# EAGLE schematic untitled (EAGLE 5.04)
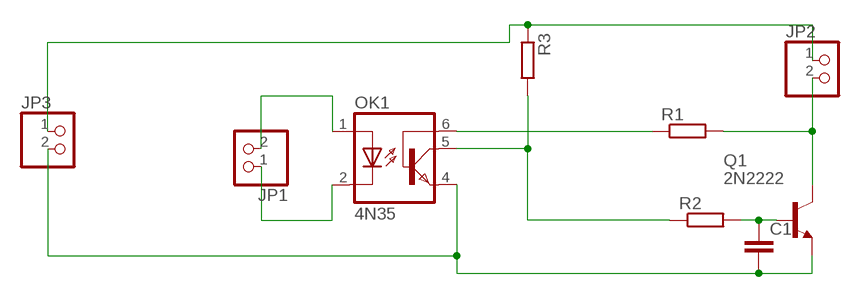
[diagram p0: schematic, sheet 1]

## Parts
C1  C-EU025-025X050  [C025-025X050]
JP1  PINHD-1X2  [1X02]
JP2  PINHD-1X2  [1X02]
JP3  PINHD-1X2  [1X02]
OK1  4N35  [DIL06]
Q1  2N2222  [TO18]
R1  R-EU_0204/5  [0204/5]
R2  R-EU_0204/5  [0204/5]
R3  R-EU_0204/5  [0204/5]

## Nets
N$1: OK1.5(COL) R2.1 R3.2
N$2: OK1.6(BAS) R1.1
N$3: JP2.2 Q1.3(C) R1.2
N$4: C1.2 JP3.2 OK1.4(EMI) Q1.1(E)
N$5: C1.1 Q1.2(B) R2.2
N$7: JP2.1 JP3.1 R3.1
N$8: JP1.1 OK1.2(C)
N$9: JP1.2 OK1.1(A)

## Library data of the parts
C1 = rcl-2:C-EU: CAPACITOR, European symbol
JP1-JP3 = pinhead:PINHD-1X2: PIN HEADER
OK1 = optocoupler:4N35: MOTOROLA OPTO COUPLER
Q1 = transistor-npn:2N2222*: NPN Transistor
R1-R3 = rcl-2:R-EU_: RESISTOR, European symbol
